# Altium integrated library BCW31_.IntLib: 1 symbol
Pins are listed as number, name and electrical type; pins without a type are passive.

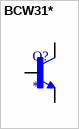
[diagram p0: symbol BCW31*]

## BCW31*
designator Q?
â€¢ This device is designed for general purpose amplifier applications at collector currents to 300 mA. â€¢ Sourced from process 10.; MF: Fairchild Semiconductor; MP: BCW31
footprint SOT23-BEC
pins: B, C, E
